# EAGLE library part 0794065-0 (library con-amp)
MINI UNIVERSAL MATE-N-LOCK (TM) Double Row Vertical 8 Pol. Source: http://catalog.tycoelectronics.com .. ENG_CD_794065_D1.pdf
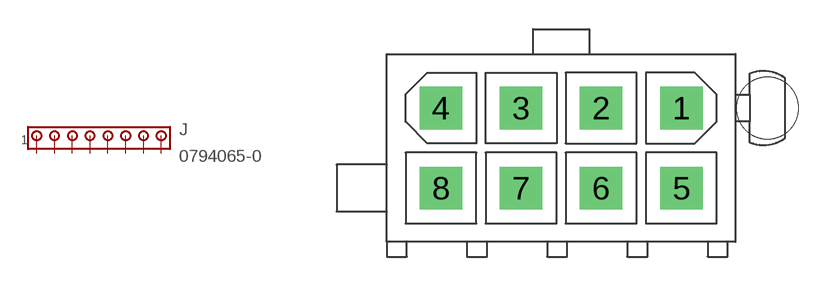
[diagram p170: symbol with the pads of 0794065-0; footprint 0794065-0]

Designator prefix J

## 0794065-0 (MPN: 1-794065-0; OC_FARNELL: 1098528; OC_NEWARK: 52K3392)  [0794065-0]
1  1  pas
2  2  pas
3  3  pas
4  4  pas
5  5  pas
6  6  pas
7  7  pas
8  8  pas

## Footprint 0794065-0 (pad centres in mm)
MINI UNIVERSAL MATE-N-LOCK (TM) Double Row Vertical 8 Pol. Source: http://catalog.tycoelectronics.com .. ENG_CD_794065_D1.pdf
drill 1.4 pad 2.2 square: 1 6.21,2.07; 2 2.07,2.07; 3 -2.07,2.07; 4 -6.21,2.07; 5 6.21,-2.07; 6 2.07,-2.07; 7 -2.07,-2.07; 8 -6.21,-2.07
hole 3.2 at 10.66,2.07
